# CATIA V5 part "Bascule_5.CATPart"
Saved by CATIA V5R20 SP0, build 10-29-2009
Part number: Bascule_5
Publications: "Corps_bascule_5", "Axe_pivot_bascule_5_point_E", "Axe_pivot_bascule_5_point_F", "Plan_ref"
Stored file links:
  C:\Users\J\IAO_2012_jgossard\Bascule_5.CATPart
  C:\Users\J\IAO_2012_jgossard\squelette_mecanisme_presse.CATProduct

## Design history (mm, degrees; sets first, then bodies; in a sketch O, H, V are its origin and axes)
Set1
  Point1 "Point_E": linked copy from another document
  Point2 "Point_F": linked copy from another document
  Plane1 "Plan_ref": linked copy from another document
Body1 (main body)
  Line1 "Corps_bascule_5": type PtPt, FirstPoint Point1, SecondPoint Point2
  Line2 "Axe_pivot_bascule_5_point_E": type Normal, RefPoint Point1, RefSkin Plane1, Start 0, End 10
  Line3 "Axe_pivot_bascule_5_point_F": type Normal, RefPoint Point2, RefSkin Plane1, Start 0, End 10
